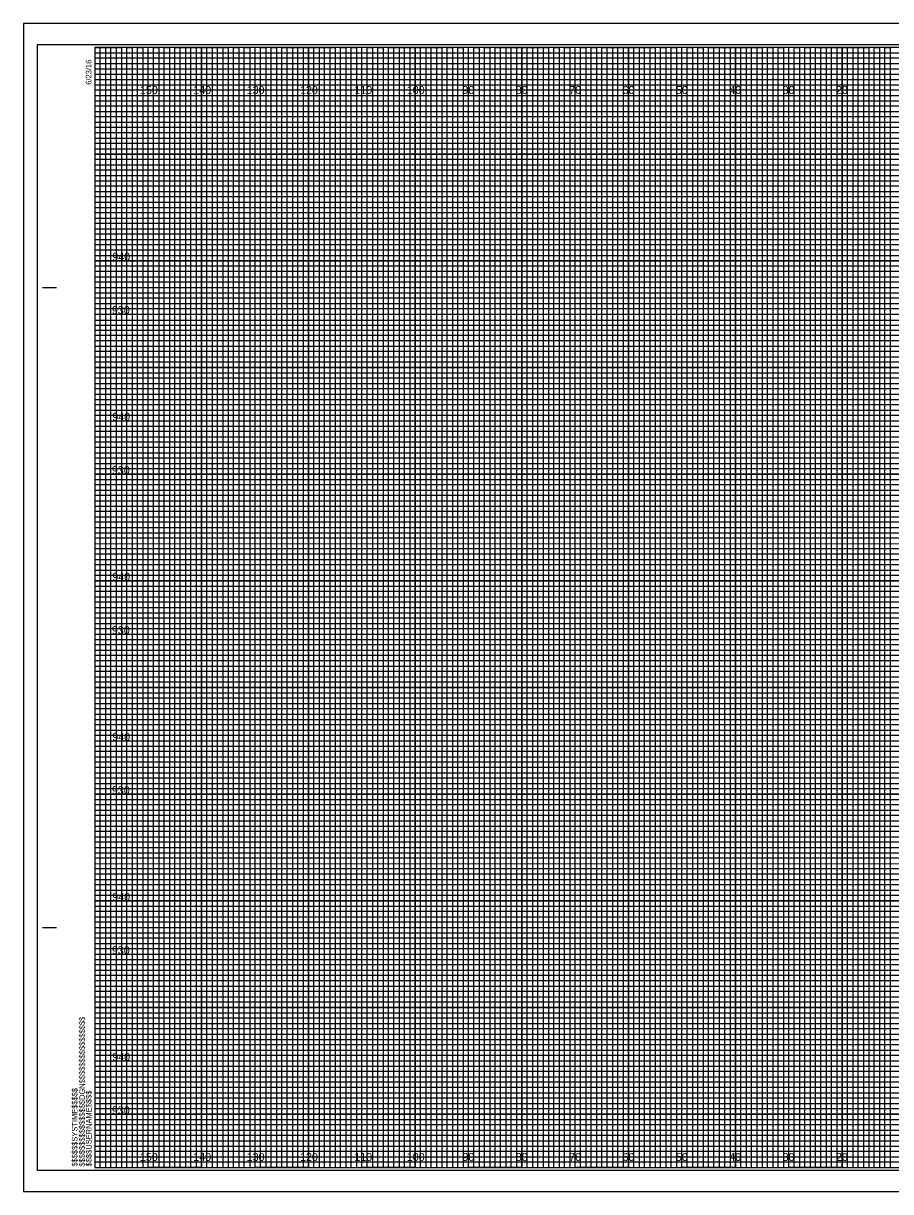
# Model space of a CAD drawing. Extents: x -13 to 323, y -4 to 214.
# Drawn here: x -13.4 to 149.1, y -4.5 to 214.5 of the extents above; entities that cross this region are included whole.
import ezdxf

# ---------------------------------------------------------------- set-up
doc = ezdxf.new("R2010")
doc.units = 0
for name, color, linetype in [('Prop XS Elevation Labels', 7, 'Continuous'), ('Prop XS Shear Point Label', 7, 'Continuous'), ('Sheet Cross Section CELL', 7, 'Continuous'), ('Sheet Cross Section Grid Major CELL', 7, 'Continuous'), ('Sheet Cross Section Grid Middle CELL', 7, 'Continuous'), ('Sheet Cross Section Grid Minor 1 CELL', 7, 'Continuous'), ('Sheet Cross Section Grid Minor 2 CELL', 7, 'Continuous'), ('Sheet Cutting Line CELL', 7, 'Continuous'), ('Sheet DOT Grid CELL', 7, 'Continuous'), ('Sheet Plot Border Inside CELL', 7, 'Continuous'), ('Sheet Plot Border Outside CELL', 7, 'Continuous')]:
    doc.layers.add(name, color=color, linetype=linetype)

msp = doc.modelspace()

# ---------------------------------------------------------------- linework, layer by layer
at = {"layer": 'Sheet Cross Section CELL'}
for p, q in [((-9.8, 165), (-7.3, 165)), ((-9.7, 165), (-7.2, 165)), ((-9.8, 45), (-7.3, 45)), ((-9.7, 45), (-7.2, 45)), ((0, 0), (0, 0)), ((0, 0), (0, 0)), ((0, 0), (0, 0)), ((0, 0), (0, 0)), ((0, 0), (0, 0)), ((0, 0), (0, 0)), ((0, 0), (0, 0))]:
    msp.add_line(p, q, dxfattribs=at)
msp.add_lwpolyline([(320, 210), (0, 210), (0, 0), (320, 0)], close=True, dxfattribs=at)
at = {"layer": 'Sheet Cross Section Grid Major CELL'}
for p, q in [((10, 210), (0, 210)), ((10, 0), (10, 210)), ((30, 210), (20, 210)), ((20, 210), (20, 0)), ((30, 0), (30, 210)), ((50, 210), (40, 210)), ((40, 210), (40, 0)), ((50, 0), (50, 210)), ((70, 210), (60, 210)), ((60, 210), (60, 0)), ((70, 0), (70, 210)), ((90, 210), (80, 210)), ((80, 210), (80, 0)), ((90, 0), (90, 210)), ((110, 210), (100, 210)), ((100, 210), (100, 0)), ((110, 0), (110, 210)), ((130, 210), (120, 210)), ((120, 210), (120, 0)), ((130, 0), (130, 210)), ((150, 210), (140, 210)), ((140, 210), (140, 0)), ((20, 0), (10, 0)), ((40, 0), (30, 0)), ((60, 0), (50, 0)), ((80, 0), (70, 0)), ((100, 0), (90, 0)), ((120, 0), (110, 0)), ((140, 0), (130, 0))]:
    msp.add_line(p, q, dxfattribs=at)
for points in [[(0, 200), (320, 200), (320, 190), (0, 190)], [(0, 180), (320, 180), (320, 170), (0, 170)], [(0, 160), (320, 160), (320, 150), (0, 150)], [(0, 140), (320, 140), (320, 130), (0, 130)], [(0, 120), (320, 120), (320, 110), (0, 110)], [(0, 100), (320, 100), (320, 90), (0, 90)], [(0, 80), (320, 80), (320, 70), (0, 70)], [(0, 60), (320, 60), (320, 50), (0, 50)], [(0, 40), (320, 40), (320, 30), (0, 30)], [(0, 20), (320, 20), (320, 10), (0, 10)]]:
    msp.add_lwpolyline(points, dxfattribs=at)
at = {"layer": 'Sheet Cross Section Grid Middle CELL'}
for points in [[(0, 210), (5, 210), (5, 0), (15, 0), (15, 210), (25, 210), (25, 0), (35, 0), (35, 210), (45, 210), (45, 0), (55, 0), (55, 210), (65, 210), (65, 0), (75, 0), (75, 210), (85, 210), (85, 0), (95, 0), (95, 210), (105, 210), (105, 0), (115, 0), (115, 210), (125, 210), (125, 0), (135, 0), (135, 210), (145, 210), (145, 0), (155, 0)], [(0, 205), (275, 205)], [(0, 185), (320, 185), (320, 195), (0, 195)], [(0, 165), (320, 165), (320, 175), (0, 175)], [(0, 145), (320, 145), (320, 155), (0, 155)], [(0, 125), (320, 125), (320, 135), (0, 135)], [(0, 105), (320, 105), (320, 115), (0, 115)], [(0, 85), (320, 85), (320, 95), (0, 95)], [(0, 65), (320, 65), (320, 75), (0, 75)], [(0, 45), (320, 45), (320, 55), (0, 55)], [(0, 25), (320, 25), (320, 35), (0, 35)], [(0, 5), (320, 5), (320, 15), (0, 15)]]:
    msp.add_lwpolyline(points, dxfattribs=at)
at = {"layer": 'Sheet Cross Section Grid Minor 1 CELL'}
for p, q in [((0, 209), (260, 209)), ((260, 207.98), (0, 207.98)), ((0, 207.98), (0, 207)), ((0, 207), (260, 207)), ((260, 205.89), (0, 205.89)), ((0, 205.89), (0, 204)), ((0, 204), (320, 204))]:
    msp.add_line(p, q, dxfattribs=at)
for points in [[(0, 203), (270, 203), (320, 203), (320, 202), (0, 202)], [(0, 201), (320, 201), (320, 199), (0, 199)], [(0, 198), (320, 198), (320, 197), (0, 196.98)], [(0, 196), (320, 196), (320, 194), (0, 194)], [(0, 193), (320, 193), (320, 192), (0, 192)], [(0, 191), (320, 191), (320, 189), (0, 189)], [(0, 188), (320, 188), (320, 187), (0, 187)], [(0, 186), (320, 186), (320, 184), (0, 184)], [(0, 183), (320, 183), (320, 182), (0, 182)], [(0, 181), (320, 181), (320, 179), (0, 179)], [(0, 178), (320, 178), (320, 177), (0, 177)], [(0, 176), (320, 176), (320, 173.95), (320, 173), (320, 172), (0, 172)], [(0, 174), (320, 174), (320, 173), (0, 173)], [(0, 171), (320, 171), (320, 169), (0, 169.03)], [(0, 169.03), (320, 169), (320, 168), (0, 168)], [(0, 167), (320, 167), (320, 166), (0, 166)], [(0, 164), (320, 164), (320, 163), (0, 163)], [(0, 162), (320, 162), (320, 161), (0, 161)], [(-0.07, 158.89), (320, 158.89), (320, 157.88), (-0.07, 157.88)], [(0, 157), (320, 157), (320, 156), (0, 156)], [(0, 154), (320, 154), (320, 153), (0, 153)], [(0, 152), (320, 152), (320, 151), (0, 151)], [(0, 149), (320, 149), (320, 148), (0, 148)], [(0, 147), (320, 147), (320, 146), (0, 146)], [(0, 144), (320, 144), (320, 143), (0, 143)], [(0, 142), (320, 142), (320, 141), (0, 141)], [(0, 139), (320, 139), (319.99, 137.98), (0, 138)], [(0, 137), (320, 137), (320, 136), (0, 136)], [(0, 134), (320, 134), (320, 133), (0, 133)], [(0, 132), (320, 132), (320, 131), (0, 131)], [(0, 129), (320, 129), (320, 128), (0, 128)], [(0, 127), (320, 127), (320, 126), (0, 126)], [(0, 124), (320, 124), (320, 123), (0, 123)], [(0, 122), (320, 122), (320, 121), (0, 121)], [(0, 119), (320, 119), (320, 118), (0, 118)], [(0, 116.99), (320.07, 116.91), (320, 116), (0, 116)], [(0, 114), (320, 114), (320, 113), (0, 113)], [(0, 112), (320, 112), (320, 111), (0, 111)], [(0, 109), (320, 109), (320, 108), (0, 108)], [(0, 107), (320, 107), (320, 106), (0, 106)], [(0, 104), (320, 104), (320, 103), (0, 103)], [(0, 102), (320, 102), (320, 101), (0, 101)], [(0, 99), (320, 99), (320, 98), (0, 98)], [(0, 97), (320, 97), (320, 96), (0, 96)], [(0, 94), (320, 94), (320, 93), (0, 93)], [(0, 92), (320, 92), (320, 91), (0, 91)], [(0, 89), (320, 89), (320, 88), (0, 88)], [(0, 87), (320, 87), (320, 86), (0, 86)], [(0, 84), (320, 84), (320, 83), (0, 83)], [(0, 82), (320, 82), (320, 81), (0, 81)], [(0, 79), (320, 79), (319.99, 77.98), (0, 78)], [(0, 77), (320, 77), (320, 76), (0, 76)], [(0, 74), (320, 74), (320, 73), (0, 73)], [(0, 72), (320, 72), (320, 71), (0, 71)], [(0, 69), (320, 69), (320, 68), (0, 68)], [(0, 67), (320, 67), (320, 66), (0, 66)], [(0, 64), (320, 64), (320, 63), (0, 63)], [(0, 62), (320, 62), (320, 61), (0, 61)], [(0, 59), (320, 59), (320, 58), (0, 58)], [(0, 56.99), (320.07, 56.91), (320, 56), (0, 56)], [(0, 54), (320, 54), (320, 53), (0, 53)], [(0, 52), (320, 52), (320, 51), (0, 51)], [(0, 49), (320, 49), (320, 48), (0, 48)], [(0, 47), (320, 47), (320, 46), (0, 46)], [(0, 44), (320, 44), (320, 43), (0, 43)], [(0, 42), (320, 42), (320, 41), (0, 41)], [(0, 39), (320, 39), (320, 38), (0, 38)], [(0, 37), (320, 37), (320, 36), (0, 36)], [(0, 34), (320, 34), (320, 33), (0, 33)], [(0, 32), (320, 32), (320, 31), (0, 31)], [(0, 29), (320, 29), (320, 28), (0, 28)], [(0, 27), (320, 27), (320, 26), (0, 26)], [(0, 24), (320, 24), (320, 23), (0, 23)], [(0, 22), (320, 22), (320, 21), (0, 21)], [(0, 19), (320, 19), (320, 18), (0, 18)], [(0, 17), (320, 17), (320, 16), (0, 16)], [(0, 14), (320, 14), (320, 13), (0, 13)], [(0, 12), (320, 12), (320, 11), (0, 11)], [(0, 9), (320, 9), (320, 8), (0, 8)], [(0, 7), (320, 7), (320, 6), (0, 6)], [(0, 4), (320, 4), (320, 3), (0, 3)], [(0, 2), (320, 2), (320, 1), (0, 1)]]:
    msp.add_lwpolyline(points, dxfattribs=at)
at = {"layer": 'Sheet Cross Section Grid Minor 2 CELL'}
for points in [[(0, 0), (1, 0), (1, 210), (2, 210), (2, 0)], [(2, 0), (3, 0), (3, 210), (4, 210), (4, 0)], [(5, 0), (6, 0), (6, 210), (7, 210), (7, 0)], [(7, 0), (8, 0), (8, 210), (9, 210), (9, 0)], [(10, 0), (11, 0), (11, 210), (12, 210), (12, 0)], [(12, 0), (13, 0), (13, 210), (14, 210), (14, 0)], [(15, 0), (16, 0), (16, 210), (17, 210), (17, 0)], [(17, 0), (18, 0), (18, 210), (19, 210), (19, 0)], [(20, 0), (21, 0), (21, 210), (22, 210), (22, 0)], [(22, 0), (23, 0), (23, 210), (24, 210), (24, 0)], [(25, 0), (26, 0), (26, 210), (27, 210), (27, 0)], [(27, 0), (28, 0), (28, 210), (29, 210), (29, 0)], [(30, 0), (31, 0), (31, 210), (32, 210), (32, 0)], [(32, 0), (33, 0), (33, 210), (34, 210), (34, 0)], [(35, 0), (36, 0), (36, 210), (37, 210), (37, 0)], [(37, 0), (38, 0), (38, 210), (39, 210), (39, 0)], [(40, 0), (41, 0), (41, 210), (42, 210), (42, 0)], [(42, 0), (43, 0), (43, 210), (44, 210), (44, 0)], [(45, 0), (46, 0), (46, 210), (47, 210), (47, 0)], [(47, 0), (48, 0), (48, 210), (49, 210), (49, 0)], [(50, 0), (51, 0), (51, 210), (52, 210), (52, 0)], [(52, 0), (53, 0), (53, 210), (54, 210), (54, 0)], [(55, 0), (56, 0), (56, 210), (57, 210), (57, 0)], [(57, 0), (58, 0), (58, 210), (59, 210), (59, 0)], [(60, 0), (61, 0), (61, 210), (62, 210), (62, 0)], [(62, 0), (63, 0), (63, 210), (64, 210), (64, 0)], [(65, 0), (66, 0), (66, 210), (67, 210), (67, 0)], [(67, 0), (68, 0), (68, 210), (69, 210), (69, 0)], [(70, 0), (71, 0), (71, 210), (72, 210), (72, 0)], [(72, 0), (73, 0), (73, 210), (74, 210), (74, 0)], [(75, 0), (76, 0), (76, 210), (77, 210), (77, 0)], [(77, 0), (78, 0), (78, 210), (79, 210), (79, 0)], [(80, 0), (81, 0), (81, 210), (82, 210), (82, 0)], [(82, 0), (83, 0), (83, 210), (84, 210), (84, 0)], [(85, 0), (86, 0), (86, 210), (87, 210), (87, 0)], [(87, 0), (88, 0), (88, 210), (89, 210), (89, 0)], [(90, 0), (91, 0), (91, 210), (92, 210), (92, 0)], [(92, 0), (93, 0), (93, 210), (94, 210), (94, 0)], [(95, 0), (96, 0), (96, 210), (97, 210), (97, 0)], [(97, 0), (98, 0), (98, 210), (99, 210), (99, 0)], [(100, 0), (101, 0), (101, 210), (102, 210), (102, 0)], [(102, 0), (103, 0), (103, 210), (104, 210), (104, 0)], [(105, 0), (106, 0), (106, 210), (107, 210), (107, 0)], [(107, 0), (108, 0), (108, 210), (109, 210), (109, 0)], [(110, 0), (111, 0), (111, 210), (112, 210), (112, 0)], [(112, 0), (113, 0), (113, 210), (114, 210), (114, 0)], [(115, 0), (116, 0), (116, 210), (117, 210), (117, 0)], [(117, 0), (118, 0), (118, 210), (119, 210), (119, 0)], [(120, 0), (121, 0), (121, 210), (122, 210), (122, 0)], [(122, 0), (123, 0), (123, 210), (124, 210), (124, 0)], [(125, 0), (126, 0), (126, 210), (127, 210), (127, 0)], [(127, 0), (128, 0), (128, 210), (129, 210), (129, 0)], [(130, 0), (131, 0), (131, 210), (132, 210), (132, 0)], [(132, 0), (133, 0), (133, 210), (134, 210), (134, 0)], [(135, 0), (136, 0), (136, 210), (137, 210), (137, 0)], [(137, 0), (138, 0), (138, 210), (139, 210), (139, 0)], [(140, 0), (141, 0), (141, 210), (142, 210), (142, 0)], [(142, 0), (143, 0), (143, 210), (144, 210), (144, 0)], [(145, 0), (146, 0), (146, 210), (147, 210), (147, 0)], [(147, 0), (148, 0), (148, 210), (149, 210), (149, 0)]]:
    msp.add_lwpolyline(points, dxfattribs=at)
at = {"layer": 'Sheet Cutting Line CELL'}
for p, q in [((323.3, 214.5), (-13.4, 214.5)), ((-13.4, 214.5), (-13.4, -4.5)), ((-13.4, -4.5), (323.3, -4.5))]:
    msp.add_line(p, q, dxfattribs=at)
at = {"layer": 'Sheet DOT Grid CELL'}
for p, q in [((10, 0), (10, 210)), ((20, 0), (20, 210)), ((30, 0), (30, 210)), ((40, 0), (40, 210)), ((50, 0), (50, 210)), ((60, 0), (60, 210)), ((70, 0), (70, 210)), ((80, 0), (80, 210)), ((90, 0), (90, 210)), ((100, 0), (100, 210)), ((110, 0), (110, 210)), ((120, 0), (120, 210)), ((130, 0), (130, 210)), ((140, 0), (140, 210)), ((0, 200), (320, 200)), ((0, 190), (320, 190)), ((0, 180), (320, 180)), ((0, 170), (320, 170)), ((0, 160), (320, 160)), ((0, 150), (320, 150)), ((0, 140), (320, 140)), ((0, 130), (320, 130)), ((0, 120), (320, 120)), ((0, 110), (320, 110)), ((0, 100), (320, 100)), ((0, 90), (320, 90)), ((0, 80), (320, 80)), ((0, 70), (320, 70)), ((0, 60), (320, 60)), ((0, 50), (320, 50)), ((0, 40), (320, 40)), ((0, 30), (320, 30)), ((0, 20), (320, 20)), ((0, 10), (320, 10))]:
    msp.add_line(p, q, dxfattribs=at)
at = {"layer": 'Sheet Plot Border Inside CELL'}
msp.add_lwpolyline([(-10.8, -0.5), (322.4, -0.5), (322.4, 210.5), (-10.8, 210.5)], close=True, dxfattribs=at)
at = {"layer": 'Sheet Plot Border Outside CELL'}
msp.add_lwpolyline([(-13.4, -4.5), (323.3, -4.5), (323.3, 214.5), (-13.4, 214.5)], close=True, dxfattribs=at)

# ---------------------------------------------------------------- texts
at = {"layer": 'Prop XS Elevation Labels'}
for s, p in [('940', (3.26, 170)), ('930', (3.18, 160)), ('940', (3.26, 140)), ('930', (3.18, 130)), ('940', (3.26, 110)), ('930', (3.18, 100)), ('940', (3.26, 80)), ('930', (3.18, 70)), ('940', (3.26, 50)), ('930', (3.18, 40)), ('940', (3.26, 20)), ('930', (3.18, 10))]:
    msp.add_text(s, height=1.5, dxfattribs=at).set_placement(p)
at = {"layer": 'Prop XS Shear Point Label'}
for s, p in [('150', (8.44, 201.25)), ('140', (18.44, 201.25)), ('130', (28.44, 201.25)), ('120', (38.44, 201.25)), ('110', (48.62, 201.25)), ('100', (58.44, 201.25)), ('90', (68.86, 201.25)), ('80', (78.86, 201.25)), ('70', (88.86, 201.25)), ('60', (98.86, 201.25)), ('50', (108.86, 201.25)), ('40', (118.86, 201.25)), ('30', (128.86, 201.25)), ('20', (138.86, 201.25)), ('150', (8.44, 1.25)), ('140', (18.44, 1.25)), ('130', (28.44, 1.25)), ('120', (38.44, 1.25)), ('110', (48.62, 1.25)), ('100', (58.44, 1.25)), ('90', (68.86, 1.25)), ('80', (78.86, 1.25)), ('70', (88.86, 1.25)), ('60', (98.86, 1.25)), ('50', (108.86, 1.25)), ('40', (118.86, 1.25)), ('30', (128.86, 1.25)), ('20', (138.86, 1.25))]:
    msp.add_text(s, height=1.5, dxfattribs=at).set_placement(p)
at = {"layer": 'Sheet Cross Section CELL'}
for s, p in [('6/23/16', (-0.65, 203)), ('$$$$$$$$$$$$$$$$DGN$$$$$$$$$$$$$$$$', (-1.88, 0.18)), ('$$$$$$SYSTIME$$$$$', (-3.26, 0.18)), ('$$$$USERNAME$$$$', (-0.62, 0.23))]:
    msp.add_text(s, height=1.05, rotation=90, dxfattribs=at).set_placement(p)

doc.saveas('drawing.dxf')
